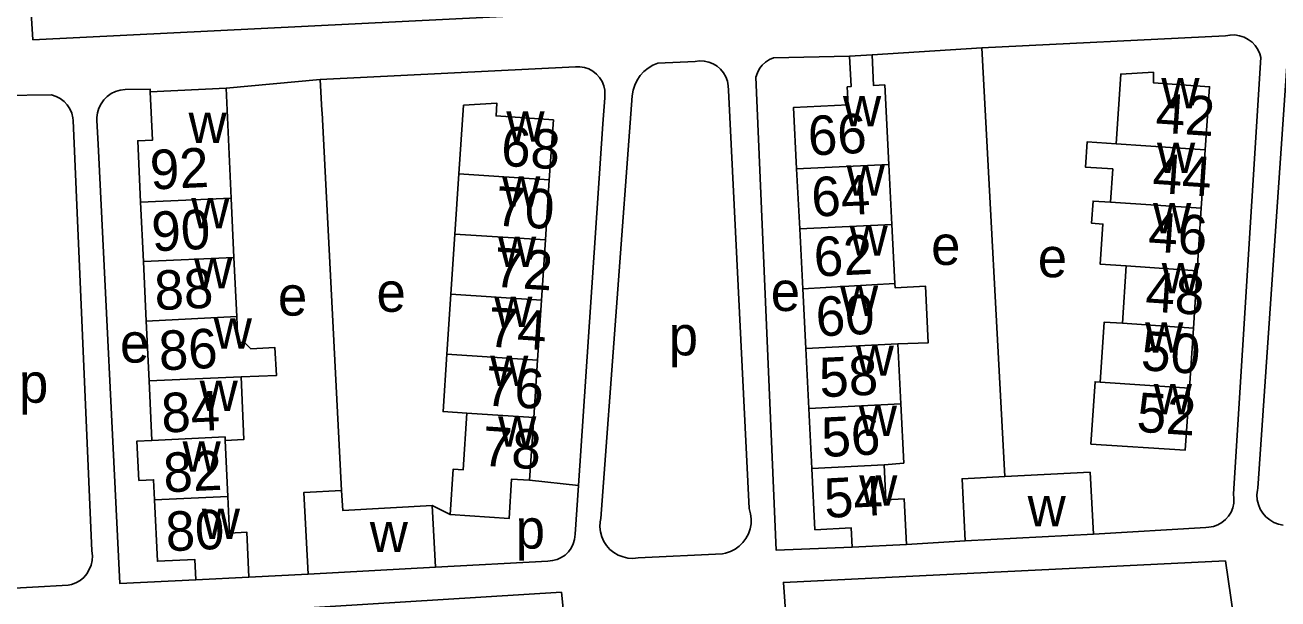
# Model space of a CAD drawing. Extents: x 159294 to 161936, y 384538 to 386517.
# Drawn here: x 161612.3 to 161739.3, y 386264.2 to 386322.4 of the extents above; entities that cross this region are included whole.
import ezdxf

# ---------------------------------------------------------------- set-up
doc = ezdxf.new("R2010")
doc.units = 0
for name, color, linetype in [('BLT_Basislijn', 7, 'Continuous'), ('BLT_Bebouwing', 7, 'Continuous'), ('BLT_Centroide', 7, 'Continuous'), ('BLT_Huisnummer', 7, 'Continuous'), ('BLT_Huisnummer_ tussenligend', 7, 'Continuous'), ('BLT_Onderverdeling_panden', 7, 'Continuous')]:
    doc.layers.add(name, color=color, linetype=linetype)

msp = doc.modelspace()

# ---------------------------------------------------------------- linework, layer by layer
at = {"layer": 'BLT_Basislijn'}
for p, q in [((161612.49, 386330.41), (161613.12, 386320.89)), ((161696.79, 386325.08), (161613.12, 386320.89)), ((161709.28, 386320.09), (161698.14, 386319.36)), ((161733.96, 386321.28), (161709.28, 386320.09)), ((161709.28, 386320.09), (161711.59, 386276.62)), ((161695.86, 386319.24), (161688.17, 386319.07)), ((161734.76, 386274.87), (161737.55, 386319.09)), ((161737.24, 386275.47), (161740.23, 386319.19)), ((161642.22, 386316.86), (161668.08, 386318.16)), ((161676.43, 386318.53), (161680.21, 386318.69)), ((161632.68, 386315.98), (161642.22, 386316.86)), ((161610.03, 386315.26), (161615.01, 386315.3)), ((161670.65, 386272.38), (161673.84, 386315.2)), ((161671.05, 386315), (161670.88, 386312.39)), ((161683.59, 386315.8), (161685.68, 386273.38)), ((161617.2, 386312.71), (161619.09, 386269.09)), ((161619.71, 386310.31), (161619.59, 386312.71)), ((161642.41, 386313.5), (161644.4, 386275.21)), ((161670.88, 386312.39), (161668.4, 386275.74)), ((161668.4, 386275.74), (161663.44, 386276.25)), ((161668.4, 386275.74), (161668.07, 386270.79)), ((161720.57, 386270.78), (161731.97, 386271.48)), ((161701.63, 386269.76), (161707.58, 386270.13)), ((161665.3, 386268.07), (161653.91, 386267.44)), ((161682.99, 386268.79), (161674.43, 386268.4)), ((161641.02, 386266.73), (161635.01, 386266.42)), ((161616.7, 386265.61), (161607.15, 386265.11))]:
    msp.add_line(p, q, dxfattribs=at)
for points in [[(161733.96, 386321.28), (161734.43, 386321.37), (161734.91, 386321.38), (161735.39, 386321.3), (161735.84, 386321.16), (161736.27, 386320.93), (161736.65, 386320.64), (161736.98, 386320.3), (161737.24, 386319.9), (161737.44, 386319.46), (161737.55, 386319.09)], [(161688.17, 386319.07), (161687.74, 386318.89), (161687.36, 386318.64), (161687.02, 386318.33), (161686.74, 386317.97), (161686.53, 386317.56), (161686.38, 386317.1)], [(161668.08, 386318.16), (161668.55, 386318.16), (161669.01, 386318.09), (161669.45, 386317.94), (161669.86, 386317.71), (161670.23, 386317.42), (161670.54, 386317.07), (161670.79, 386316.68), (161670.96, 386316.24), (161671.06, 386315.79), (161671.08, 386315.32), (161671.05, 386315)], [(161676.43, 386318.53), (161675.92, 386318.31), (161675.45, 386318.03), (161675.02, 386317.68), (161674.65, 386317.27), (161674.34, 386316.81), (161674.09, 386316.31), (161673.93, 386315.79), (161673.84, 386315.2)], [(161680.21, 386318.69), (161680.67, 386318.75), (161681.14, 386318.74), (161681.61, 386318.64), (161682.04, 386318.47), (161682.45, 386318.22), (161682.8, 386317.92), (161683.1, 386317.55), (161683.34, 386317.14), (161683.5, 386316.7), (161683.58, 386316.24), (161683.59, 386315.8)], [(161642.41, 386313.5), (161642.4, 386313.72), (161642.22, 386316.86)], [(161686.38, 386317.1), (161688.44, 386269.16), (161696.13, 386269.48)], [(161615.01, 386315.3), (161615.46, 386315.15), (161615.89, 386314.93), (161616.27, 386314.64), (161616.59, 386314.29), (161616.86, 386313.89), (161617.05, 386313.45), (161617.17, 386312.99), (161617.2, 386312.71)], [(161625.01, 386315.62), (161624.99, 386315.9), (161622.45, 386315.86), (161621.96, 386315.8), (161621.49, 386315.66), (161621.05, 386315.44), (161620.65, 386315.16), (161620.31, 386314.81), (161620.02, 386314.41), (161619.8, 386313.97), (161619.66, 386313.5), (161619.59, 386313.02), (161619.59, 386312.71)], [(161629.61, 386266.17), (161621.91, 386265.8), (161619.71, 386310.31)], [(161734.76, 386274.87), (161734.82, 386274.4), (161734.8, 386273.93), (161734.7, 386273.47), (161734.52, 386273.03), (161734.27, 386272.62), (161733.96, 386272.27), (161733.6, 386271.97), (161733.18, 386271.74), (161732.74, 386271.58), (161732.27, 386271.49), (161731.97, 386271.48)], [(161739.81, 386271.69), (161739.33, 386271.79), (161738.87, 386271.97), (161738.44, 386272.23), (161738.06, 386272.54), (161737.74, 386272.92), (161737.48, 386273.34), (161737.29, 386273.79), (161737.18, 386274.27), (161737.15, 386274.77), (161737.2, 386275.26), (161737.24, 386275.47)], [(161655.38, 386272.78), (161653.56, 386273.7)], [(161685.68, 386273.38), (161685.83, 386272.87), (161685.89, 386272.35), (161685.88, 386271.83), (161685.79, 386271.32), (161685.62, 386270.82), (161685.37, 386270.36), (161685.06, 386269.94), (161684.69, 386269.57), (161684.27, 386269.26), (161683.8, 386269.02), (161683.3, 386268.86), (161682.99, 386268.79)], [(161846.76, 386273.88), (161822.75, 386272.48), (161822.95, 386266.5), (161800.85, 386265.71), (161800.45, 386271.68), (161755.86, 386269.09), (161756.26, 386263.52), (161734.76, 386262.52), (161733.96, 386268.1)], [(161674.43, 386268.4), (161673.92, 386268.34), (161673.41, 386268.37), (161672.91, 386268.48), (161672.43, 386268.67), (161671.99, 386268.92), (161671.59, 386269.24), (161671.25, 386269.63), (161670.97, 386270.05), (161670.76, 386270.52), (161670.62, 386271.02), (161670.57, 386271.53), (161670.59, 386272.04), (161670.65, 386272.38)], [(161665.3, 386268.07), (161665.77, 386268.11), (161666.23, 386268.22), (161666.65, 386268.42), (161667.04, 386268.68), (161667.38, 386269.01), (161667.66, 386269.39), (161667.87, 386269.8), (161668.01, 386270.26), (161668.07, 386270.79)], [(161619.09, 386269.09), (161619.14, 386268.61), (161619.12, 386268.12), (161619.01, 386267.65), (161618.83, 386267.2), (161618.58, 386266.78), (161618.26, 386266.41), (161617.89, 386266.1), (161617.47, 386265.85), (161617.01, 386265.68), (161616.7, 386265.61)], [(161733.96, 386268.1), (161689.17, 386265.91), (161689.57, 386260.13), (161667.27, 386258.93), (161666.67, 386264.91), (161631.24, 386262.72)]]:
    msp.add_lwpolyline(points, dxfattribs=at)
at = {"layer": 'BLT_Bebouwing'}
for p, q in [((161625.01, 386315.62), (161632.68, 386315.98)), ((161632.68, 386315.98), (161633.2, 386304.85)), ((161656.27, 386307.3), (161656.73, 386314.27)), ((161665.85, 386312.78), (161665.44, 386306.7)), ((161731.91, 386309.74), (161731.51, 386303.82)), ((161690.5, 386307.81), (161690.81, 386301.74)), ((161700.15, 386302.18), (161699.84, 386308.24)), ((161665.44, 386306.7), (161665.04, 386300.61)), ((161633.2, 386304.85), (161633.49, 386298.84)), ((161624.31, 386298.41), (161624.03, 386304.45)), ((161731.51, 386303.82), (161731.09, 386297.49)), ((161655.46, 386295.12), (161655.87, 386301.21)), ((161690.81, 386301.74), (161691.12, 386295.67)), ((161700.45, 386296.19), (161700.15, 386302.18)), ((161665.04, 386300.61), (161664.64, 386294.52)), ((161633.49, 386298.84), (161633.77, 386292.85)), ((161624.59, 386292.38), (161624.31, 386298.41)), ((161723.91, 386297.97), (161723.53, 386292.16)), ((161731.09, 386297.49), (161730.7, 386291.67)), ((161655.06, 386289.04), (161655.46, 386295.12)), ((161691.12, 386295.67), (161691.42, 386289.6)), ((161664.64, 386294.52), (161664.24, 386288.43)), ((161624.88, 386286.34), (161624.59, 386292.38)), ((161730.7, 386291.67), (161730.3, 386285.6)), ((161691.42, 386289.6), (161691.73, 386283.52)), ((161701.06, 386284.01), (161700.76, 386290.07)), ((161664.24, 386288.43), (161663.86, 386282.62)), ((161625.16, 386280.3), (161624.88, 386286.34)), ((161691.73, 386283.52), (161692.04, 386277.45)), ((161663.86, 386282.62), (161663.44, 386276.25)), ((161632.86, 386274.61), (161632.6, 386280.3)), ((161711.59, 386276.62), (161720.25, 386277.06)), ((161720.25, 386277.06), (161720.57, 386270.78)), ((161653.56, 386273.7), (161653.91, 386267.44)), ((161720.57, 386270.78), (161707.58, 386270.13)), ((161701.63, 386269.76), (161696.13, 386269.48)), ((161653.91, 386267.44), (161641.02, 386266.73)), ((161635.01, 386266.42), (161629.61, 386266.17))]:
    msp.add_line(p, q, dxfattribs=at)
for points in [[(161695.86, 386319.24), (161696.02, 386316.15), (161695.63, 386316.12), (161695.72, 386314.3), (161690.18, 386314.02), (161690.5, 386307.81)], [(161695.86, 386319.24), (161698.14, 386319.36)], [(161699.84, 386308.24), (161699.43, 386316.32), (161698.3, 386316.26), (161698.14, 386319.36)], [(161731.91, 386309.74), (161732.34, 386316.14), (161726.67, 386316.53), (161726.65, 386317.61), (161723.34, 386317.42), (161722.87, 386310.35)], [(161625.01, 386315.62), (161625.24, 386310.73), (161623.74, 386310.66), (161624.03, 386304.45)], [(161656.73, 386314.27), (161660.13, 386314.46), (161660.05, 386313.17), (161665.85, 386312.78)], [(161722.87, 386310.35), (161719.94, 386310.54), (161719.77, 386308), (161722.54, 386307.81), (161722.32, 386304.44)], [(161655.87, 386301.21), (161656.27, 386307.3)], [(161722.32, 386304.44), (161720.54, 386304.55), (161720.39, 386302.3), (161721.54, 386302.22), (161721.27, 386298.14), (161723.91, 386297.97)], [(161700.76, 386290.07), (161703.82, 386290.18), (161703.55, 386295.94), (161700.47, 386295.76), (161700.45, 386296.19)], [(161634.2, 386286.72), (161637.78, 386286.87), (161637.64, 386289.7), (161635.21, 386289.58), (161634.54, 386290.23), (161633.89, 386290.2), (161633.77, 386292.85)], [(161723.53, 386292.16), (161721.67, 386292.29), (161721.26, 386286.21)], [(161657.08, 386283.07), (161654.68, 386283.22), (161655.06, 386289.04)], [(161632.6, 386280.3), (161634.5, 386280.39), (161634.2, 386286.72)], [(161721.26, 386286.21), (161720.74, 386286.24), (161720.32, 386279.93), (161729.87, 386279.3), (161730.3, 386285.6)], [(161699.36, 386277.82), (161701.36, 386277.99), (161701.06, 386284.01)], [(161655.38, 386272.78), (161655.69, 386277.37), (161656.7, 386277.3), (161657.08, 386283.07)], [(161625.16, 386280.3), (161623.66, 386280.23), (161623.85, 386276.24), (161625.35, 386276.3), (161625.44, 386274.26)], [(161692.04, 386277.45), (161692.04, 386277.45), (161692.36, 386271.24), (161696.03, 386271.43), (161696.13, 386269.48)], [(161699.36, 386277.82), (161699.54, 386274.27), (161701.4, 386274.36), (161701.63, 386269.76)], [(161663.44, 386276.25), (161661.62, 386276.37), (161661.36, 386272.38), (161655.38, 386272.78)], [(161707.58, 386270.13), (161707.26, 386276.41), (161711.59, 386276.62)], [(161632.86, 386274.61), (161633.04, 386270.9), (161634.8, 386270.98), (161635.01, 386266.42)], [(161641.02, 386266.73), (161640.56, 386275), (161644.4, 386275.21)], [(161644.4, 386275.21), (161644.51, 386273.2), (161653.56, 386273.7)], [(161629.61, 386266.17), (161629.51, 386268.23), (161625.73, 386268.05), (161625.44, 386274.26)]]:
    msp.add_lwpolyline(points, dxfattribs=at)
at = {"layer": 'BLT_Onderverdeling_panden'}
for p, q in [((161722.87, 386310.35), (161731.91, 386309.74)), ((161690.5, 386307.81), (161699.84, 386308.24)), ((161665.44, 386306.7), (161656.27, 386307.3)), ((161624.03, 386304.45), (161633.2, 386304.85)), ((161731.51, 386303.82), (161722.32, 386304.44)), ((161665.04, 386300.61), (161655.87, 386301.21)), ((161690.81, 386301.74), (161700.15, 386302.18)), ((161633.49, 386298.84), (161624.31, 386298.41)), ((161723.91, 386297.97), (161731.09, 386297.49)), ((161700.45, 386296.19), (161691.12, 386295.67)), ((161664.64, 386294.52), (161655.46, 386295.12)), ((161624.59, 386292.38), (161633.77, 386292.85)), ((161730.7, 386291.67), (161723.53, 386292.16)), ((161691.42, 386289.6), (161700.76, 386290.07)), ((161664.24, 386288.43), (161655.06, 386289.04)), ((161634.2, 386286.72), (161624.88, 386286.34)), ((161721.26, 386286.21), (161730.3, 386285.6)), ((161701.06, 386284.01), (161691.73, 386283.52)), ((161663.86, 386282.62), (161657.08, 386283.07)), ((161699.36, 386277.82), (161692.04, 386277.45)), ((161625.44, 386274.26), (161632.86, 386274.61))]:
    msp.add_line(p, q, dxfattribs=at)
msp.add_lwpolyline([(161625.16, 386280.3), (161632.58, 386280.64), (161632.6, 386280.3)], dxfattribs=at)

# ---------------------------------------------------------------- texts
at = {"layer": 'BLT_Centroide'}
for s, p in [('w', (161727.46, 386313.94)), ('w', (161695.2, 386312.12)), ('w', (161628.88, 386310.45)), ('w', (161661.09, 386310.56)), ('w', (161727.02, 386307.38)), ('w', (161695.56, 386305.09)), ('w', (161660.66, 386303.97)), ('w', (161629.16, 386301.78)), ('w', (161726.62, 386301.28)), ('w', (161695.87, 386299)), ('e', (161704.13, 386298.08)), ('w', (161660.25, 386297.88)), ('e', (161714.94, 386296.83)), ('w', (161629.44, 386295.69)), ('w', (161727.5, 386295.19)), ('e', (161637.94, 386292.94)), ('e', (161647.93, 386293.33)), ('e', (161687.88, 386293.41)), ('w', (161694.9, 386292.91)), ('w', (161659.86, 386291.78)), ('w', (161631.44, 386289.59)), ('w', (161725.82, 386289.19)), ('e', (161621.94, 386288.18)), ('p', (161677.54, 386288.91)), ('w', (161696.49, 386286.84)), ('w', (161659.45, 386285.81)), ('p', (161611.7, 386284.11)), ('w', (161630.01, 386283.28)), ('w', (161726.69, 386282.94)), ('w', (161696.8, 386280.75)), ('w', (161660.26, 386279.66)), ('w', (161628.28, 386277.12)), ('w', (161696.84, 386273.69)), ('w', (161713.91, 386271.59)), ('w', (161630.23, 386270.31)), ('w', (161647.25, 386268.97)), ('p', (161662.03, 386269.33))]:
    msp.add_text(s, height=4, dxfattribs=at).set_placement(p)
at = {"layer": 'BLT_Huisnummer'}
for s, rotation, p in [('42', 356.173, (161726.8, 386311.52)), ('66', 2.9129, (161691.74, 386309.15)), ('68', 356.2302, (161660.47, 386308.14)), ('92', 2.684, (161625.07, 386305.71)), ('46', 356.1687, (161726.05, 386299.46)), ('62', 2.9129, (161692.34, 386296.88)), ('72', 356.2298, (161659.72, 386295.88)), ('88', 2.6864, (161625.52, 386293.48)), ('58', 2.9129, (161692.89, 386284.65)), ('84', 2.6852, (161626.21, 386281.07)), ('52', 356.1737, (161724.88, 386281.18)), ('78', 356.2274, (161658.54, 386277.74)), ('54', 2.9129, (161693.37, 386272.43)), ('80', 2.6838, (161626.65, 386269.05))]:
    msp.add_text(s, height=4, rotation=rotation, dxfattribs=at).set_placement(p)
at = {"layer": 'BLT_Huisnummer_ tussenligend'}
for s, rotation, p in [('44', 356.173, (161726.49, 386305.4)), ('64', 2.9129, (161692.09, 386302.95)), ('70', 356.2302, (161659.88, 386302.08)), ('90', 2.6864, (161625.22, 386299.45)), ('48', 356.1687, (161725.76, 386293.39)), ('60', 2.9129, (161692.54, 386290.82)), ('74', 356.2298, (161659.12, 386289.82)), ('86', 2.6852, (161625.96, 386287.38)), ('50', 356.1687, (161725.32, 386287.42)), ('76', 356.2298, (161658.83, 386283.85)), ('56', 2.9129, (161693.12, 386278.6)), ('82', 2.6838, (161626.42, 386275.02))]:
    msp.add_text(s, height=4, rotation=rotation, dxfattribs=at).set_placement(p)

doc.saveas('drawing.dxf')
